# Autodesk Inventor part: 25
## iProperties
Created: 2012-01
Part Number: 25
Document SubType Name: Modeling
Designer: Administrator
Density: 2.71 g/cm^3
Material: Aluminum-6061
Mass: 360.408 g
Surface Area: 434.602 cm^2
Volume: 132.992 cm^3
Translation Standard: STEP AP214IS
FileName: 21_0978_0_2.stp
PreProcessor: ACIS
PostProcessor: Build: 236a, Release: 2009 RTM - Date: Fri 02/22/2008
Sent Units: CM
Uncertainty: 0.0
Author: Administrator
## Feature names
1. Base1
